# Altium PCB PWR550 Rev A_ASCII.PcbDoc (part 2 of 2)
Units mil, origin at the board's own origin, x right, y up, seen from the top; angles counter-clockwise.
Board outline 5200 x 2850 mil, 4 copper layers (Top Layer, INTERNAL 1, INTERNAL 2, Bottom Layer), stack 60.3 mil thick; 145 components, 78 nets, 363 pads, 156 vias.
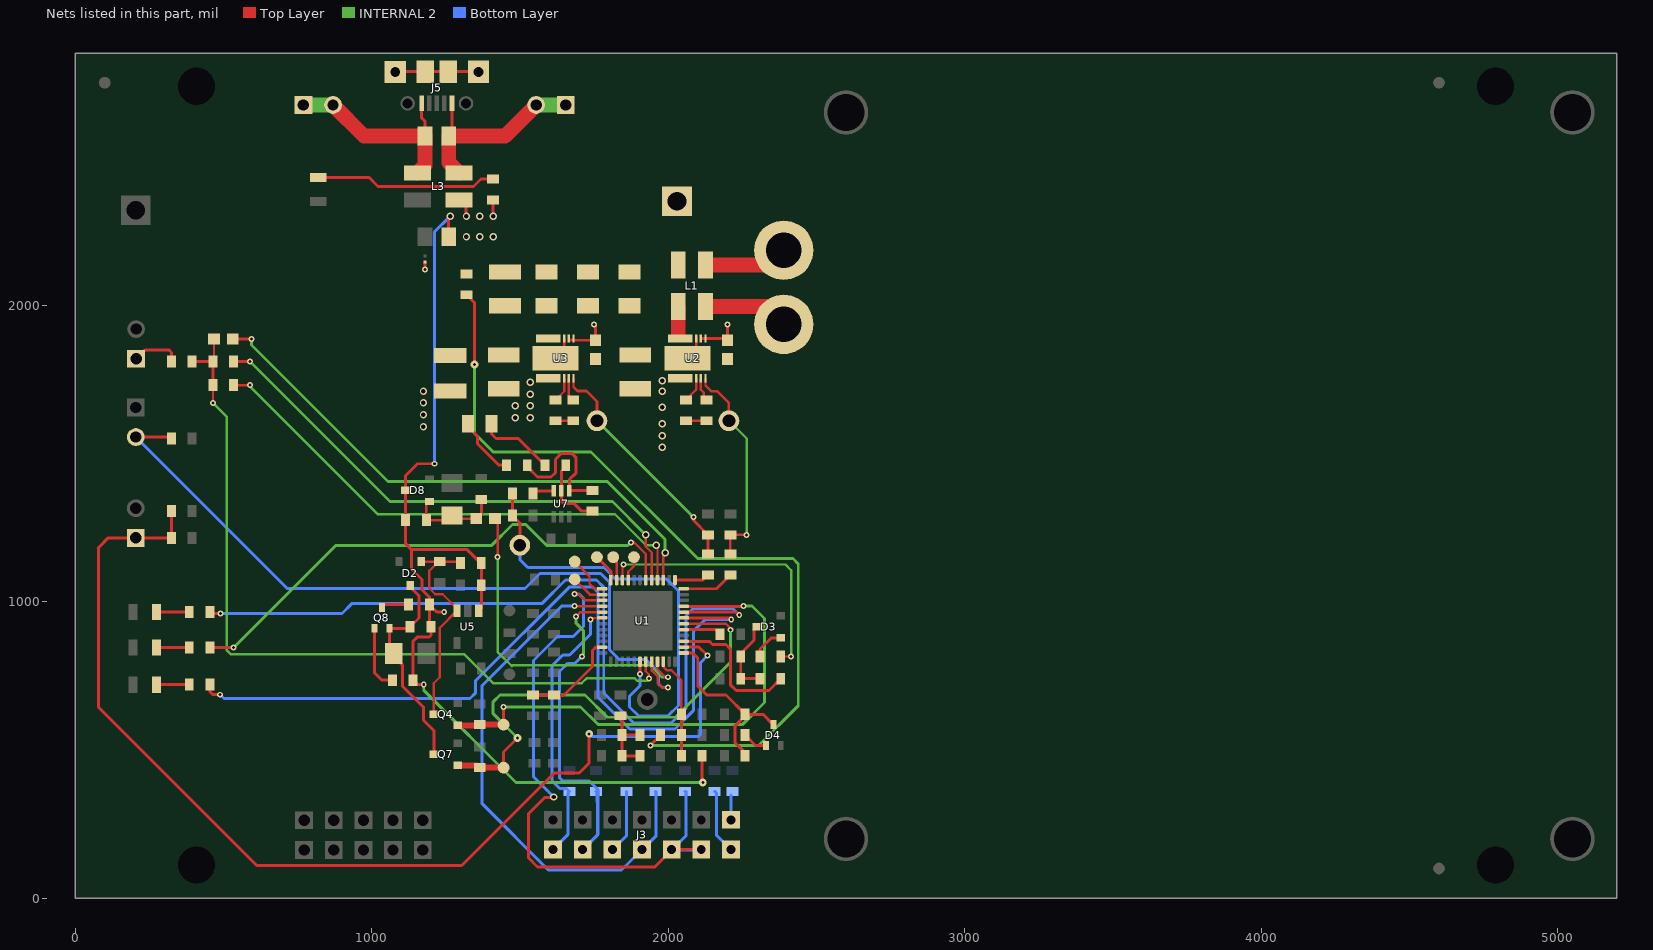
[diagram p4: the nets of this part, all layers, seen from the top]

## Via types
v1: diameter 25, hole 15, Top Layer to Bottom Layer, tented both sides, 50 vias
v2: diameter 20, hole 10, Top Layer to Bottom Layer, tented both sides, 47 vias
v3: diameter 26, hole 10, Top Layer to Bottom Layer, tented both sides, 34 vias
v4: diameter 23.62, hole 11.81, Top Layer to Bottom Layer, tented bottom, 25 vias

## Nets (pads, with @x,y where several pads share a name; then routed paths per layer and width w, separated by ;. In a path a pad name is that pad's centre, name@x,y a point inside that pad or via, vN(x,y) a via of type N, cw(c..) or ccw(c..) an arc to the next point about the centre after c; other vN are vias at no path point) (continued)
DPWM-1A: R2.1 R17.2 TP3.1 U2.8 | length 717.4
  Top Layer w8: U2.8@2126.02,1753.07 2126.02,1728.98 2145,1710 2165,1710 2205,1670 TP3.1@2205,1610 ; R2.1@2210,1160 R17.2@2210,1225 v2(2265,1225)
  INTERNAL 2 w8: TP3.1@2205,1610 2265,1550 v2(2265,1225)
DPWM-1B: R47.1 R48.2 TP2.1 U3.8 | length 798.7
  Top Layer w8: U3.8@1681.02,1753.07 1681.02,1723.98 1695,1710
  Top Layer w10: 1695,1710 1725,1710 1760,1675 TP2.1@1760,1610 ; v2(2085,1285) 2085,1275 R48.2@2135,1225 R47.1@2135,1160
  INTERNAL 2 w10: TP2.1@1760,1610 v2(2085,1285)
GND: 1A1.1 C7.1 C9.2 C13.2 C23.2 C33.2 U2.3 U2.9 U3.3 U3.9 | length 129.3
  Top Layer w8: U3.9@1649.53,1820 U3.3@1649.53,1886.93 ; U2.9@2094.53,1849.53 U2.3@2094.53,1886.93
  Top Layer w10: v2(1180,2120) 1A1.1@1180,2145
I_SENSE: C16.2 R46.1 TP19.1 U1.42 | length 1557.6
  Top Layer w10: R46.1@1475,1365 C16.2@1475,1290 1500,1265 TP19.1@1500,1190 ; v2(1905.2,756.27) U1.42@1905.2,797.6
  Bottom Layer w10: TP19.1@1500,1190 1500,1142 1527,1115 1783.5,1115 1823,1075.5 1995.37,1075.5 2035,1035.87 2035,650 2000,615 1900,615 1870,645 1870,681.06 1905.2,716.26 v2(1905.2,756.27) ; v2@1900,754.8 v2@1900.2,755
LED_A: R15.1 U1.7 | length 2850.3
  Top Layer w10: R15.1@455,720 455,696 465,686 v2(489,686) ; U1.7@2052.5,944.9 2207.1,944.9 v2(2213,939) ; v2@2209.8,939.8 v2@2209.8,940
  Bottom Layer w10: v2(489,686) 502,673 1332,673 1350,691 1350,732 1668,1050 1745,1050 1763,1032 1763,678.06 1871.06,570 2023,570 2085,632 2085,900 2120,935 cw(c2129.66,925.34) 2129.66,939 v2(2213,939)
LED_B: R16.1 U1.8 | length 2799.2
  Top Layer w10: R16.1@455,965 455,960 485,960 v2(490,960) ; U1.8@2052.5,964.6 2229.6,964.6 2239.2,955 v2(2240,955)
  Bottom Layer w10: v2(490,960) 485,960 900,960 933,993 1574,993 1654,1073 1758.25,1073 1783,1048.25 1783,692 1885,590 2010,590 2060,640 2060,952 2085,977 2218,977 v2(2240,955)
LED_C: R50.1 U1.18 | length 1779
  Top Layer w8: v2(1875,1200) 1885,1200 1924.9,1160.1 U1.18@1924.9,1072.6
  Top Layer w10: R50.1@455,845 v2(535,845)
  INTERNAL 2 w10: v2(535,845) 880,1190 1405,1190 1475,1260 1520,1260 1590,1190 1865,1190 v2(1875,1200)
NetC4_1: C4.1 R10.1 R11.2 U1.46 | length 352.2
  Top Layer w8: U1.46@1985,796.6 1985,779 1994.9,769.1 2010.9,769.1 2045,735 C4.1@2045,620
  Top Layer w10: U1.46@1984,797.6 U1.46@1985,796.6 ; R10.1@2045,480 R11.2@2045,550 C4.1@2045,620
NetC6_1: C6.1 U2.7 | length 81.2
  Top Layer w8: U2.7@2110.28,1753.07 2110.28,1715 2120,1705.28 2120,1690 C6.1@2130,1680
NetC6_2: C6.2 R3.1 | length 70
  Top Layer w10: R3.1@2060,1610 C6.2@2130,1610
NetC8_2: C8.2 C20.1 U1.35 | length 331
  Top Layer w10: C8.2@1545,685 C20.1@1615,685 1649,685 1745,781 1745,835 1756.4,846.4 U1.35@1777.5,846.4
NetC10_2: C10.2 D4.3 R8.2 U1.1 | length 627.3
  Top Layer w10: U1.1@2052.5,826.7 2083.3,826.7 2100,810 2100,715 2130,685 2195,685 C10.2@2260,620 ; R8.2@2260,480 2260,490 2225,525 2225,580 2260,615 C10.2@2260,620 ; D4.3@2355,585 2320,620 C10.2@2260,620
NetC11_1: C11.1 D3.3 R28.2 R30.1 | length 262.7
  Top Layer w10: D3.3@2299.75,915 2290,905.25 2290,870 2245,825 C11.1@2245,815 R28.2@2245,740 R30.1@2310,740
NetC12_2: C12.2 D8.1 R45.2 R51.2 R54.1 | length 317.5
  Top Layer w8: D8.1@1195.25,1337.6 1185,1327.35 R54.1@1185,1275 1255,1275 1270,1290 1280,1280 R45.2@1353.5,1280
  Top Layer w10: R45.2@1353.5,1280 1370,1296.5 R51.2@1370,1345
NetC14_2: C14.2 R5.2 R6.1 R14.1 R29.1 | length 260
  Top Layer w10: R29.1@1840,615 1845,615 R5.2@1845,550 ; R14.1@1905,480 C14.2@1845,480 R5.2@1845,550 ; R6.1@1905,550 R5.2@1845,550
NetC15_1: C15.1 R1.2 | length 60
  Top Layer w10: R1.2@1620,1610 C15.1@1680,1610
NetC15_2: C15.2 U3.7 | length 79.2
  Top Layer w8: U3.7@1665.28,1753.07 1665.28,1694.72 C15.2@1680,1680
NetC17_1: C17.1 J1.1 J1.2 J5.1 L3.1 | length 693
  Top Layer w10: C17.1@1260,2570 1271.18,2581.18 J5.1@1271.18,2681.42
  Top Layer w50: L3.1@1295,2446 1260,2481 C17.1@1260,2570 1450,2570 J1.2@1555,2675
  INTERNAL 2 w50: J1.2@1555,2675 J1.1@1655,2675
NetC17_2: C17.2 J2.1 J2.2 J5.5 L3.4 | length 703.9
  Top Layer w10: J5.5@1168.82,2681.42 1168.82,2631.18 1180,2620 C17.2@1180,2570
  Top Layer w50: J2.2@870,2675 975,2570 C17.2@1180,2570 1180,2471 L3.4@1155,2446
  INTERNAL 2 w50: J2.1@770,2675 J2.2@870,2675
NetC18_1: C18.1 R6.2 | length 2835
  Top Layer w10: C18.1@1320,2035 1347,2008 v3(1347,1800) ; v2@1940,515 R6.2@1975,550
  INTERNAL 2 w10: v3(1347,1800) 1347,1568 1410,1505 1740,1505 2100,1145 2421.21,1145 2439,1127.21 2439,649 2305,515 v2@1940,515
  other v2: 1940.8,515
NetC18_2: C18.2 C27.2 C28.2 C29.2 C30.2 L1.3 TP1.1
NetC22_2: C22.2 D2.1 Q4.3 R25.1 U5.3 | length 745.4
  Top Layer w8: D2.1@1167.65,1135 C22.2@1220,1135 ; Q4.3@1209.75,620 1209.75,724.75 1230,745 1230,911.5 U5.3@1288,969.5 1288,977 1240,1025 1215,1025 1195,1045 1195,1104 1220,1129 C22.2@1220,1135 ; R25.1@1300,1130 1295,1135 C22.2@1230,1135 C22.2@1220,1135
NetC23_1: C23.1 C33.1 R32.1 R36.1 U2.5 U3.5 | length 258.5
  Top Layer w10: R32.1@1405,1600 1405,1565 1420,1550 1495,1550 R36.1@1585,1460
  other v1: 1980,1520 1980,1560 1980,1600 1485,1620 1535,1620 1980,1655 1485,1660 1535,1660 1535,1700 1980,1710 1535,1740 1980,1745
NetC24_1: C24.1 JP1.1 R19.1 U1.2 | length 3755
  Top Layer w10: C24.1@325,1305 R19.1@325,1215 JP1.1@205,1215 112,1215 79,1182 79,644 613,110 1304,110 1616,422 1700,422 1734,456 v3(1734,554) ; U1.2@2052.5,846.4 2104.6,846.4 v2(2133,818)
  Bottom Layer w10: v3(1734,554) 1743,545 2102,545 2110,553 2110,795 v2(2133,818)
NetC27_1: C27.1 C28.1 C29.1 C30.1 U3.4
NetC31_1: C31.1 R36.2 U7.5 | length 251.6
  Top Layer w10: R36.2@1655,1460 1655,1445 1645,1445 1640.1,1440.1 U7.5@1640.1,1373.6 1640,1373.5 1640,1340 1650,1330 1683.7,1330 1708.7,1305 C31.1@1745,1305
NetC31_2: C31.2 R37.2 U7.4 | length 447
  Top Layer w10: R37.2@1525,1460 1525,1455 1560,1420 1605,1420 1620,1435 1620,1480 1640,1500 1675,1500 1690,1485 1690,1435 1667.5,1412.5 1667.5,1375 C31.2@1745,1375
NetC32_1: C32.1 D2.3 Q7.3 Q8.1 R53.1 | length 680.7
  Top Layer w10: C32.1@1060,840 Q8.1@1060,910 R53.1@1125,910 ; C32.1@1075,815 1105,785 1105,714 1175,644 1175,600 1209.75,565.25 Q7.3@1209.75,485 ; R53.1@1130,915 1160,945 1160,1020 D2.3@1130,1050
NetC34_1: C34.1 Q8.2 | length 220.4
  Top Layer w10: Q8.2@1010,910 1010,760 1035,735 C34.1@1070,735
NetD1_2: D1.2 R4.1 | length 612.8
  Top Layer w10: D1.2@820,2430 992,2430 1022,2400 1344,2400 1369,2425 R4.1@1410,2425
NetD3_1: D3.1 R33.1 | length 110.8
  Top Layer w10: R33.1@2310,815 2310,840 2347.6,877.6 D3.1@2380.25,877.6
NetD4_1: D4.1 R12.2 | length 84.5
  Top Layer w10: R12.2@2260,550 2295,515 D4.1@2330,515
NetD5_2: D5.2 R15.2 | length 110
  Top Layer w10: D5.2@275,720 R15.2@385,720
NetD7_2: D7.2 R16.2 | length 110
  Top Layer w10: D7.2@275,965 R16.2@385,965
NetD9_2: D9.2 R50.2 | length 110
  Top Layer w10: D9.2@275,845 R50.2@385,845
NetJ3_5: J3.5 R49.2 | length 216.5
  Bottom Layer w10: J3.5@1812,164 1860,210 R49.2@1860,360
NetJ3_13: J3.13 R31.2 | length 220.5
  Bottom Layer w10: R31.2@2157,360 2162.5,354.5 2162.5,212.5 J3.13@2212.5,162.5
NetJ3_14: J3.14 R21.2 | length 85
  Bottom Layer w10: J3.14@2212.5,262.5 2212.5,264 R21.2@2212.5,347.5
NetJ5_6: J5.6 J5.7 J5.8 J5.9 | length 280.5
  Top Layer w10: J5.9@1079.84,2787.32 1080.24,2787.72 1180.63,2787.72 1258.98,2787.72 J5.6@1360.16,2787.72
NetJP2_2: JP2.2 R23.2 U1.44 | length 2587.9
  Top Layer w8: U1.44@1944.6,797.6 1944.6,767.4 1965,747 1965,725 1980,710 v2(2000,710)
  Top Layer w10: JP2.2@205,1555 320,1555 R23.2@325,1550
  Bottom Layer w10: JP2.2@205,1555 715.5,1044.5 1517.5,1044.5 1568,1095 1772.5,1095 1802,1065.5 1802,838 1835,805 1925,805 1968.5,761.5 1968.5,721.5 1980,710 v2(2000,710)
NetJP3_1: JP3.1 R22.1 | length 180.1
  Top Layer w10: JP3.1@206,1819 225,1815 225,1837 237,1849 316,1849 325,1840 R22.1@325,1810
NetL1_1: L1.1 L2.2 | length 324
  Top Layer w10: L2.2@2330,1995 2390,1995 L2.2@2390,1935
  Top Layer w50: L1.1@2126,1995 L2.2@2330,1995
NetL1_2: L1.2 U2.4 | length 98.7
  Top Layer w10: U2.4@2034,1886.93 U2.4@2041.38,1886.93
  Top Layer w50: 2034,1903.72 L1.2@2034,1995
NetL1_4: L1.4 L2.1 | length 284.7
  Top Layer w50: L1.4@2126,2135 2340,2135 L2.1@2390,2185
NetQ8_3: Q8.3 R55.1 | length 105
  Top Layer w10: Q8.3@1035,980 1035,990 R55.1@1130,990
NetR1_1: R1.1 U3.6 | length 85.3
  Top Layer w8: R1.1@1620,1680 1649.53,1709.53 U3.6@1649.53,1753.07
NetR2_2: R2.2 U1.12 | length 176.8
  Top Layer w10: U1.12@2052.5,1043.4 2163.4,1043.4 R2.2@2210,1090
NetR3_2: R3.2 U2.6 | length 87.4
  Top Layer w8: R3.2@2060,1680 2094.53,1714.53 U2.6@2094.53,1753.07
NetR9_1: R9.1 U1.5 | length 135.9
  Top Layer w10: U1.5@2052.5,905.5 2159.5,905.5 R9.1@2175,890 R9.1@2175,897
NetR22_2: R22.2 R24.1 R27.1 R99.1 U1.43 | length 2679.5
  Top Layer w8: v2(465,1670) R27.1@465,1730 ; R24.1@468.5,1813.5 R99.1@468.5,1885 ; U1.43@1924.9,797.6 1924.9,765.1 1935,755 v2(1935,740)
  Top Layer w10: R22.2@395,1810 R24.1@465,1810 R27.1@465,1730
  INTERNAL 2 w8: v2(465,1670) 512,1623 512,835.47 525.47,822 1313,822 1410,725 1709,725 1726,742 1886.95,742 1895.67,733.27 1928.27,733.27 v2(1935,740)
NetR24_2: R24.2 U1.17 | length 1792.8
  Top Layer w8: v1(1925,1225) 1925,1185 1944.6,1165.4 U1.17@1944.6,1072.6
  Top Layer w10: R24.2@535,1810 v2(590,1810)
  INTERNAL 2 w10: v2(590,1810) 1062.12,1337.88 1812.12,1337.88 v1(1925,1225)
NetR27_2: R27.2 U1.16 | length 1770.8
  Top Layer w8: R27.2@535,1730 v2(590,1730) ; v1(1960,1190) 1964.3,1185.7 U1.16@1964.3,1072.6
  INTERNAL 2 w8: v2(590,1730) 590,1725 1020,1295 1820,1295 1925,1190 v1(1960,1190)
NetR46_2: R46.2 U7.6 | length 77.7
  Top Layer w10: R46.2@1545,1365 1545,1373.6 U7.6@1614.1,1373.6
NetR47_2: R47.2 U1.13 | length 118.8
  Top Layer w10: U1.13@2023.4,1072.6 2117.6,1072.6 R47.2@2135,1090
NetR99_2: R99.2 U1.15 | length 1889.7
  Top Layer w8: U1.15@1984,1072.6 1984,1159 v1(1990,1165)
  Top Layer w10: R99.2@531.5,1885 v2(595,1885)
  INTERNAL 2 w10: v2(595,1885) 595,1865 1055,1405 1795,1405 1990,1210 v1(1990,1165)
NetTP18_1: TP18.1 U1.21 | length 85.4
  Top Layer w8: U1.21@1865.8,1072.6 1865.8,1100.8 1885,1120 TP18.1@1885,1150
NetTP25_1: TP25.1 U1.26 | length 113.7
  Top Layer w8: TP25.1@1685,1075 1736.3,1023.7 U1.26@1777.5,1023.7
NetTP26_1: TP26.1 U1.25 | length 145.1
  Top Layer w8: TP26.1@1685,1135 1735,1085 1735,1060 1751.6,1043.4 U1.25@1777.5,1043.4
NetTP27_1: TP27.1 U1.24 | length 96.7
  Top Layer w10: TP27.1@1760,1150 1806.7,1103.3 U1.24@1806.7,1072.6
NetTP28_1: TP28.1 U1.23 | length 82.1
  Top Layer w8: TP28.1@1815,1150 1826.4,1138.6 U1.23@1826.4,1072.6
PWR_UP: R45.1 U1.45 | length 1135.2
  Top Layer w8: R45.1@1416.5,1280 1425,1271.5 v2(1425,1150) ; U1.45@1964.3,797.6 1964.3,771.7 1991,745 v2@1997.79,745
  INTERNAL 2 w8: v2(1425,1150) 1425,830 1472.5,782.5 ; 1472.5,785 1939.12,785 1979.12,745 v2(2000,745)
SLEEP: Q7.1 R52.2 TP20.1 U1.6 | length 1636.4
  Top Layer w8: U1.6@2052.5,925.2 2194.8,925.2 2215,905 v2(2210,905)
  Top Layer w10: TP20.1@1445,440 1445,493 v3(1492,540)
  Top Layer w20: Q7.1@1290.25,447.6 1357.4,447.6 R52.2@1365,440 TP20.1@1445,440
  INTERNAL 2 w10: v3(1492,540) 1410,622 1410,662 1433,685 1720,685 1795,610 2025,610 2210,795 v2(2210,905)
SNOOZE: Q4.1 R18.2 TP14.1 U1.9 | length 1724.8
  Top Layer w10: TP14.1@1445,585 v2(1445,645) ; U1.9@2052.5,984.3 2254.3,984.3 v2(2255,985)
  Top Layer w20: Q4.1@1290.25,582.6 1362.6,582.6 R18.2@1365,585 TP14.1@1445,585
  INTERNAL 2 w10: v2(1445,645) 1705,645 1765,585 2250,585 2325,660 2325,943 2283,985 v2(2255,985)
SNOOZE_CAP: R30.2 U1.3 | length 483.2
  Top Layer w10: U1.3@2052.5,866.1 2138.9,866.1 2150,855 2195,855 2210,840 2210,720 2230,700 2340,700 R30.2@2380,740
SNOOZE_CHG: R33.2 U1.22 | length 954.7
  Top Layer w8: U1.22@1846.1,1072.6 1846.1,1121.1 v2(1850,1125) ; R33.2@2380,815 v2(2415,815)
  INTERNAL 2 w8: v2@1850,1130 1855,1125 2395.53,1125 2415,1105.53 v2(2415,815)
TCK: J3.9 J3.11 R35.2 U1.27 | length 2230.6
  Top Layer w8: v2(1685,1025) 1700,1025 1721,1004 U1.27@1777.5,1004
  Top Layer w10: v1@1615,340 1585,340 1530,285 1530,135 1560,105 1955,105 2012.5,162.5 J3.11@2110,165 ; J3.9@2012,164 2095,165 J3.11@2110,165 ; J3.11@2112.5,162.5 J3.11@2110,165
  Bottom Layer w10: v1(1614,341) 1546,409 1546,801 1627,882 1680,882 1714,916 1714,1011 1700,1025 v2(1685,1025) ; R35.2@2057,360 2060,360 2060,210 2012.5,162.5 J3.11@2112.5,162.5
TDI: J3.3 R39.2 U1.29 | length 1290
  Top Layer w8: v2(1690,950) 1704.6,964.6 U1.29@1777.5,964.6
  INTERNAL 2 w10: v2(1690,950) 1690,927 1715,902 1715,820 v2(1710,815)
  Bottom Layer w10: v2@1710,816 1686,792 1662,792 1634,764 1634,406 1645,395 1734,395 1763,366 1763,215 1762.5,214.5 ; R39.2@1757,360 1761,360 1761,355 1760,355 1762.5,290 1762.5,214.5 ; 1762.5,214.5 1762.5,212.5 1712.5,162.5 J3.3@1712,164 1762.5,214.5
TDO: J3.7 R38.2 U1.28 | length 1796.5
  Top Layer w8: v2@1685.7,984.3 U1.28@1777.5,984.3
  Top Layer w10: v2(1685,985) v2@1685.7,984.3
  Bottom Layer w10: v2(1685,985) 1641,985 1373,717 1373,318 1596,95 1843,95 J3.7@1912,164 1912.5,162.5 1960,210 1960,360 R38.2@1957,360
TMS: J3.1 R42.2 U1.30 | length 947.5
  Top Layer w8: v2(1738,939) 1743.9,944.9 U1.30@1777.5,944.9
  Bottom Layer w10: J3.1@1612,164 1662,214 1662,355 R42.2@1667,360 1657,370 1635,370 1608,397 1608,783 1645,820 1668.26,820 1738,889.74 v2@1738,936.9 ; v2@1735.9,939 v2@1738,936.9 ; v2(1738,939) v2@1738,936.9
VIN: C2.1 C7.2 C9.1 C13.1 C26.2 C34.2 D8.3 L3.2 R4.2 R10.2 R25.2 R32.2 R37.1 R53.2 R54.2 R55.2 U2.1 U2.2 U3.1 U3.2 U5.1 | length 4146.7
  Top Layer w10: v2(1176,721) 1154,721 C34.2@1140,735 1140,866.28 1153.72,880 1194,880 1200,886 R53.2@1200,915 1195,920 R55.2@1195,990 ; v2(1212,1465) 1155,1465 1114.75,1424.75 D8.3@1114.75,1375 1115,1374.75 R54.2@1115,1275 1115,1195 1135,1175 ; v2(1245,965) 1220,965 R55.2@1195,990 ; C2.1@1260,2230 1260,2295 v1(1265,2300) ; L3.2@1295,2354 1318,2354 1318,2302 v1(1320,2300) ; R32.2@1325,1600 1325,1590 1357.5,1557.5 1357.5,1532.5 1430,1460 R37.1@1455,1460 ; U5.1@1362,969.5 1362,977.5 1370,977.5 C26.2@1370,1055 R25.2@1370,1128 ; R25.2@1370,1130 R25.2@1370,1128 ; v1(1410,2300) R4.2@1410,2355 ; 1670,1881.93 1681.02,1881.93 1686.46,1881.5 C13.1@1755,1881.5 1755,1930 v2(1750,1935) ; U2.2@2113,1886.93 U2.1@2126.02,1886.93 2194.57,1886.93 C9.1@2200,1881.5 v2(2200,1935) ; R10.2@2115,480 2115,392 v3(2117,390) ; 1135,1175 1135,1110 1170,1075 1170,1040 1195,1015 R55.2@1195,990 ; 1135,1175 1323,1175 R25.2@1370,1128
  INTERNAL 2 w10: v2(1176,721) 1176,701.37 1487.37,390 v3(2117,390)
  Bottom Layer w10: v2(1212,1465) 1212,2247 v1(1265,2300)
  other v1: 1175,1590 1175,1630 1175,1670 1175,1710 1320,2230 1365,2230 1410,2230 1365,2300
pads on no net: D2.2 D3.2 D4.2 D8.2 FID1.1 FID2.1 FID3.1 J3.6 J4.1 J4.2 J4.3 J4.4 J4.5 J4.7 J4.8 J5.2 J5.3 J5.4 J5.10 J5.11 SH-J1.0 U1.4 U1.14 U1.19 U1.41 U5.4

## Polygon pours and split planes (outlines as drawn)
NetC23_1 on Top Layer "NetC23-1-1" (solid, pour order 81): 1825,1765 2035,1765 2035,1505 1825,1505
NetC23_1 on Top Layer "NetC23-1" (solid, pour order 80): 1385,1765 1635,1765 1635,1582.19 1630.1,1570 1385,1570
VIN on Top Layer "Top-Vin-4" (solid, pour order 78): 1140,1729.37 1344.37,1729.37 1345,1730 1345,1570 1140,1570
NetC18_2 on Top Layer "NETC18-2" (solid, pour order 82): 2080,2305 2080,2085 1300,2085 1300,2155 1980,2155 1980,2305
GND on Top Layer "Top-GND-1" (solid, pour order 83): 1140,2155 2240,2155 2240,1680 1140,1680
AGND on Top Layer "Top-AGND 3" (solid, remove dead copper, pour order 84): 2600,2520 2600,1477.5 2487.5,1477.5 2487.5,1360 2600,1360 2600,335 5127.5,335 5127.5,2520
VIN on Top Layer "Top-VIN-3" (solid, pour order 77): 1250,2370 1430,2370 1430,2200 1250,2200
NetC27_1 on Top Layer "NETC27-1" (solid, pour order 79): 1925,2025 1925,1960 1635,1960 1635,1890 1560,1890 1560,1960 1395,1960 1395,2025
AGND on Top Layer "Top-No Net" (solid, pour order 85): 25,2390.78 2555,2390.78 2560,2395 2560,25 25,25
VIN on INTERNAL 2 "VIN" (solid, pour order 90): 655,2450 2220,2450 2220,1890 2225,1885 2210,1870 655,1870
AGND on INTERNAL 2 "INTERNAL 2-AGND 1" (solid, remove dead copper, pour order 91): 35,425 2535,425 2535,2430 35,2430
NetC23_1 on INTERNAL 2 "INTERNAL 2-C23_1-1" (solid, pour order 89): 1385,1765 2010,1765 2010,1500 1385,1500
VIN on INTERNAL 2 "Vin" (solid, pour order 88): 1145,1875 1145,1455 1155,1445 1300,1445 1300,1755 1300,1875
AGND on INTERNAL 1 "INTERNAL 1-AGND" (solid, remove dead copper, pour order 87): 35,20 2535,20 2535,2430 35,2430
GND on INTERNAL 1 "INTERNAL 1-GND-1" (solid, pour order 86): 1140,2155 2240,2155 2240,1680 1140,1680
AGND on Bottom Layer "Bottom-AGND 3" (solid, remove dead copper, pour order 93): 31.01,2375.25 2431.01,2375.25 2431.01,45.25 31.01,45.25
AGND on Bottom Layer "Bottom-AGND 4" (solid, remove dead copper, pour order 92): 2600,2520 2600,335 5127.5,335 5127.5,2520

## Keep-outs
Keep-Out Layer:
  the board outline again, w10
  text ".Layer_Name" at 577,-858.49 h60

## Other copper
Top Layer:
  text ".Layer_Name" at 577,-858.49 h60
INTERNAL 1:
  text ".Layer_Name" at 569,-860.49 h60
INTERNAL 2:
  text ".Layer_Name" at 578,-860 h60
Bottom Layer:
  text ".Layer_Name" at 577,-858.49 h60
Multi-Layer:
  lines w10: 6489,-374 6489,-219

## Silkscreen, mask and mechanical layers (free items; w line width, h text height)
Top Overlay:
  lines w3.94: 878.53,1169.78 880,1171.26 880,1270 1020,1270 1020,1170 ; 880,1170 1020,1170 ; 1040,1090 1060,1090 ; 1205,1160 1195,1170 1020,1170 ; 2130,655 2145,670 2400,670 2430,640 ; 2290,470 2310,450 2430,450 ; 2430,450 2430,320 2530,320 2530,450 2430,450 ; 2430,640 2430,500 2530,500 2530,640 2430,640 ; 935,1020 935,1065 935,1150 1040,1150 1040,1020 935,1020
  lines w8: 1655,1105 1660,1100
  lines w40: 2812.5,357.5 2812.5,2457.5 4912.5,2457.5 4912.5,357.5 2812.5,357.5
  text "GND" at 466,2635 h125
  text "5 VDC" at 1750,2630 h125
  text "R20" at 1100,2360 h50 r90
  text "R13" at 1380,2360 h50 r90
  text "R44" at 1980,2100 h50 r90
  text "LOSS THR" at 40,2000 h75
  text "R34" at 1980,1960 h50 r90
  text "1" at 1715,1670 h25
  text "PWM2" at 2265,1580 h50
  text "PWM1" at 1680,1490 h50
  text "LED MODE" at 40,1410 h75
  text "ISENS" at 1440,1110 h50
  text "NTC" at 150,1080 h75
  text "COM+" at 1980,660 h50
  text "STATUS" at 110,560 h75
  text "bq500212AEVM-550" at 3011,153 h200
  text "PWR550A" at 3753,53 h90
  text "1" at 1387.5,30 h25
  text "1" at 540,27.5 h25
  text ".Layer_Name" at 577,-858.49 h60
Bottom Overlay:
  text ".Layer_Name" at 577,-858.49 h60
Top Paste:
  text ".Layer_Name" at 577,-858.49 h60
Bottom Paste:
  text ".Layer_Name" at 577,-858.49 h60
Top Solder:
  text ".Layer_Name" at 577,-858.49 h60
  text ".Layer_Name" at 577,-858.49 h60
Bottom Solder:
  text ".Layer_Name" at 577,-858.49 h60
Drill Guide:
  text ".Layer_Name" at 577,-858.49 h60
M1 Board Outline:
  text ".Layer_Name" at 577,-858.49 h60
M2 Board Dimensions:
  rectangle: 124.5,-410.5 499.5,-285.5
  rectangle: -0.5,-285.5 124.5,-160.5
  lines w7: -0.5,-285.5 999.5,-285.5 ; 124.5,-410.5 124.5,-160.5 ; 249.5,-410.5 249.5,-160.5 ; 499.5,-410.5 499.5,-160.5 ; 749.5,-410.5 749.5,-160.5 ; -0.5,-410.5 -0.5,-160.5 999.5,-160.5 999.5,-410.5 -0.5,-410.5
  text ".Layer_Name" at 577,-858.49 h60
M3 3D STEP Top:
  text ".Layer_Name" at 577,-858.49 h60
M4 3D STEP Bottom:
  text ".Layer_Name" at 577,-858.49 h60
M5 Assembly Top:
  lines w7: 6428,-263.5 7553,-263.5 ; 6428,-141 7550.5,-141 ; 6743,-383.5 6743,-21 ; 7128,-383.5 6428,-383.5 ; 7128,-21 6428,-21 ; 6428,-383.5 7553,-383.5 7553,-21 6428,-21 ; 6428,-383.5 6428,-21
  lines w10: -292,-930.17 6308,-930.17 ; -292,-726.83 6310,-726.83 ; -292,-523.5 -292,-1133.5 3713,-1133.5 6310,-1133.5 6310,-523.5 -291.5,-523.5 -291.5,-1133.5 1284,-1133.5 ; 2173,-1133.5 2173,-523.5 ; 3440,-726.83 3440,-523.5 ; 4280,-726.83 4280,-523.5 ; 4902,-1140 4902,-937.17
  text "TABLE 1" at 6815.5,14 h40
  text "Variant" at 6453,-96 h40
  text "Label text" at 6888,-96 h40
  text "001" at 6520.5,-216 h40
  text "ChangeMe!" at 6798,-218.5 h40
  text "COMPONENTS MARKED 'DNP' SHOULD NOT BE POPULATED, AND MAY NOT BE IN BILL OF MATERIALS" at 1153.5,-318.5 h60
  text "002" at 6520.5,-341 h40
  text "ChangeMe!" at 6793,-343.5 h40
  text "ASSEMBLY VARIANT:" at 1153,-434 h60
  text ".VariantName" at 2189,-434 h60
  text "PCB VIEWED FROM TOP SIDE" at -228.5,-655.67 h60
  text "BOARD #:" at 2248,-655.67 h60
  text ".PRJ_Number" at 2793.5,-655.67 h60
  text "REV:" at 3638,-655.67 h60
  text ".PCB_Rev" at 3929.5,-655.67 h60
  text "SVN REV:" at 4476,-655.67 h60
  text ".VersionControl_RevNumber" at 4982,-655.67 h60
  text "IGNORE ->" at -228.5,-858.49 h60
  text "PLOT NAME =" at -228.5,-1064.34 h60
  text ".plot_File_Name" at 577,-1064.34 h60
  text "GENERATED    :" at 2250,-1064.34 h60
  text ".Print_Date" at 3119.5,-1064.34 h60
  text ".Print_Time" at 3848.5,-1064.34 h60
  text "TEXAS INSTRUMENTS" at 5113,-1064.34 h60
M6 Assembly Bottom:
  lines w10: -292.5,-727.33 6309.5,-727.33 ; -290.5,-930.67 6309.5,-930.67 ; 1115.5,-1140.5 1115.5,-937.67 ; 1737.5,-727.33 1737.5,-524 ; 2577.5,-727.33 2577.5,-524 ; 3844.5,-1134 3844.5,-524 ; 4733.5,-1134 6309,-1134 6309,-524 -292.5,-524 -292.5,-1134 2304.5,-1134 6309.5,-1134 6309.5,-524
  text "COMPONENTS MARKED 'DNP' SHOULD NOT BE POPULATED, AND MAY NOT BE IN BILL OF MATERIALS" at 6102,-318 h60
  text ".VariantName" at 5058,-434 h60
  text "ASSEMBLY VARIANT:" at 6097,-434 h60
  text ".VersionControl_RevNumber" at 1035.5,-656.17 h60
  text "SVN REV:" at 1541.5,-656.17 h60
  text ".PCB_Rev" at 2088,-656.17 h60
  text "REV:" at 2379.5,-656.17 h60
  text ".PRJ_Number" at 3224,-656.17 h60
  text "BOARD #:" at 3769.5,-656.17 h60
  text "PCB VIEWED FROM BOTTOM SIDE" at 6246,-656.17 h60
  text "IGNORE ->" at 2547.85,-858.49 h60
  text "TEXAS INSTRUMENTS" at 904.5,-1064.84 h60
  text ".Print_Time" at 2169,-1064.84 h60
  text ".Print_Date" at 2898,-1064.84 h60
  text "GENERATED    :" at 3767.5,-1064.84 h60
  text ".plot_File_Name" at 5440.5,-1064.84 h60
  text "PLOT NAME =" at 6246,-1064.84 h60
M9 Title Sheet:
  lines w10: -491.5,1041.5 -291.5,1041.5 ; -491.5,3416.5 -291.5,3416.5 ; -491.5,5791.5 -291.5,5791.5 ; 2008.5,-1333.5 2008.5,-1133.5 ; 2008.5,7966.5 2008.5,8166.5 ; 4508.5,-1333.5 4508.5,-1133.5 ; 4508.5,7966.5 4508.5,8166.5 ; 6321,-1133.5 6321,-523.5 11303.5,-523.5 ; 7008.5,-1333.5 7008.5,-1133.5 ; 7008.5,7966.5 7008.5,8166.5 ; 9508.5,-1333.5 9508.5,-1133.5 ; 9508.5,7966.5 9508.5,8166.5 ; 11303.5,-1133.5 11303.5,-523.5 ; 11303.5,-823.5 14303.5,-823.5 ; 11303.5,-223.5 14303.5,-223.5 ; 11304.5,370.5 14304.5,370.5 ; 12008.5,-1333.5 12008.5,-1133.5 ; 12008.5,7966.5 12008.5,8166.5 ; 12808.5,-1123.5 12808.5,-523.5 ; 14303.5,-523.5 11303.5,-523.5 ; 14303.5,76.5 11303.5,76.5 ; 14308.5,66.5 14308.5,-1133.5 ; 14308.5,871 11304.5,871 11303.5,871 11303.5,370.5 11303.5,76.5 ; 14308.5,1041.5 14508.5,1041.5 ; 14308.5,3416.5 14508.5,3416.5 ; 14308.5,5791.5 14508.5,5791.5 ; 11303.5,-523.5 11303.5,76.5 ; 14308.5,-1133.5 -291.5,-1133.5 -291.5,7966.5 14308.5,7966.5 14308.5,-1133.5 ; -491.5,-1333.5 14508.5,-1333.5 14508.5,8166.5 -491.5,8166.5 -491.5,-1333.5
  text "1" at 739.84,8036.5 h70
  text "2" at 3235.5,8036.5 h70
  text "3" at 5724.84,8036.5 h70
  text "4" at 8231.51,8036.5 h70
  text "5" at 10730.5,8036.5 h70
  text "6" at 13235.5,8036.5 h70
  text "A" at -416.5,6893.5 h70
  text "A" at 14383.5,6893.5 h70
  text "B" at -416.5,4513.5 h70
  text "B" at 14383.5,4513.5 h70
  text "C" at -416.5,2138.5 h70
  text "C" at 14383.5,2138.5 h70
  text "PROJECT TITLE:" at 11343.5,277.5 h45
  text ".PRJ_Title" at 11393.5,144.17 h70
  text "DESIGNED FOR:" at 11343.5,-23.5 h45
  text ".PRJ_Customer" at 11393.5,-163.5 h70
  text "D" at -416.5,-231.5 h70
  text "D" at 14383.5,-231.5 h70
  text "FILE NAME:" at 11343.5,-323.5 h45
  text ".PCB_File_Name_No_Path" at 11393.5,-443.5 h70
  text "Texas Instruments (TI) and/or its licensors do not warrant the accuracy or completeness of this specification" at 6374,-605.34 h45
  text "ENGINEER:" at 11343.5,-613.5 h45
  text "LAYOUT BY:" at 12848.5,-613.5 h45
  text "or any information contained therein. TI and/or its licensors do not warrant that this design will meet" at 6329.01,-718 h45
  text ".PRJ_Engineer" at 11393.5,-768.49 h70
  text ".PCB_Layout" at 12899,-768.49 h70
  text "the specifications, will be suitable for your application or fit for any particular purpose, or will operate in" at 6329.01,-830.67 h45
  text ".Layer_Name" at 577,-858.49 h60
  text "ALTIUM DESIGNER VERSION:" at 12848.5,-923.5 h45
  text "an implementation. TI and/or its licensors do not warrant that the design is production worthy. You should" at 6329.01,-943.33 h45
  text "completely validate and test your design implementation to confirm the system functionality for your application." at 6374,-1056 h45
  text ".print_Scale" at 11393.5,-1056.83 h70
  text ".Application_BuildNumber" at 12899,-1056.83 h70
  text "1" at 739.84,-1263.5 h70
  text "2" at 3235.5,-1263.5 h70
  text "3" at 5724.84,-1263.5 h70
  text "4" at 8231.51,-1263.5 h70
  text "5" at 10730.5,-1263.5 h70
  text "6" at 13235.5,-1263.5 h70
M10 Fab Notes:
  drawing of 203 lines, arcs and shapes, not listed
  text "DESIGN INFORMATION" at 12381.02,6810 h60
  text "(REFER ALSO ARRAY/PANEL PROFILING INFORMATION)" at 12019.46,6648.29 h60
  text "BOARD SIZE" at 11333.46,6644 h60
  text "5200MIL" at 11795.78,6516.18 h60
  text "X" at 12301.46,6516.18 h60
  text "2850MIL" at 12532.78,6516.18 h60
  text "Number of Layers :" at 11736.46,6319 h60
  text "4" at 12831.27,6309 h60
  text "MIN. TRACK WIDTH:" at 11736.46,6180 h60
  text "8" at 12832.7,6180 h60
  text "MIL" at 12987.46,6180 h60
  text "MIN. CLEARANCE:" at 11736.46,6048 h60
  text "7" at 12832.7,6048 h60
  text "MIL" at 12987.46,6048 h60
  text "MIN. VIA PAD SIZE:" at 11736.46,5916 h60
  text "20" at 12802.71,5916 h60
  text "MIL" at 12987.46,5916 h60
  text "0.127mm (5MIL)" at 12431.46,5774.29 h60
  text "MINIMUM ANNULAR RING" at 11407.23,5770 h60
  text "EXTERNAL" at 13139.46,5770 h60
  text "PER" at 11607.23,5652 h60
  text "IPC-D-275 CLASS 2 LEVEL C" at 11827.23,5652 h60
  text "MIL, HOLES" at 13315.46,5539.71 h60
  text "+/-" at 12923,5539 h60
  text "+/-" at 13777,5539 h60
  text "REGISTRATION TOLERANCES:" at 11407.23,5534 h60
  text "METAL" at 12607,5534 h60
  text "5" at 13183.2,5534 h60
  text "3" at 14016.2,5534 h60
  text "MIL" at 14132.46,5534 h60
  text "MATERIAL:" at 11332.46,5324.54 h60
  text "FR-4 High Tg" at 12318.9,5184.21 h60
  text "FR-4" at 11793.46,5175.64 h60
  text "X" at 12165.46,5175.64 h60
  text "OTHER" at 13241.46,5175.64 h60
  text "62 MIL (1.6mm) +/-10%" at 12073.56,5012.92 h60
  text "THICKNESS:" at 11407.23,5008.64 h60
  text "X" at 11945.4,5008.64 h60
  text "OTHER" at 13358.46,5008.64 h60
  text "TOLERANCE:" at 11407.23,4850.64 h60
  text "X" at 12246.53,4850.64 h60
  text "ANSI IPC-6012 TYPE 3 CLASS 2" at 12433.48,4850.64 h60
  text "OTHER +/-" at 12433.46,4694.64 h60
  text "BOW & TWIST:" at 11407.23,4537.64 h60
  text "X" at 12246.53,4537.64 h60
  text "ANSI IPC-6012 TYPE 3 CLASS 2" at 12433.48,4537.64 h60
  text "OTHER +/-" at 12433.46,4379.13 h60
  text "COPPER THICKNESS (FINISHED):" at 11332.46,4243.64 h60
  text "1.4MIL (1oz)" at 12212.46,4090.92 h60
  text "2MIL (1.4oz)" at 12979.46,4090.92 h60
  text "2.8MIL (2oz)" at 13706.46,4090.92 h60
  text "OUTER:" at 11689.46,4086.64 h60
  text "X" at 13580,4084 h60
  text "1.4MIL (1oz)" at 12562.46,3933.92 h60
  text "2.8MIL (2oz)" at 13406.46,3933.92 h60
  text "INNER SIGNAL:" at 11689.46,3929.64 h60
  text "X" at 13283,3920 h60
  text "DRILLING:" at 11332.46,3790.64 h60
  text "REFERENCE:" at 11407.23,3673.64 h60
  text "X" at 12055.46,3673.64 h60
  text "AS SHOWN" at 12242.46,3673.64 h60
  text "X" at 12956.46,3673.64 h60
  text "NC_DRILL FILES" at 13093.46,3673.64 h60
  text "PTH MIN COPPER THICKNESS:" at 11407.23,3515.64 h60
  text "X" at 12757.46,3515.64 h60
  text "1MIL" at 12894.46,3515.64 h60
  text "OTHER" at 13391.46,3515.64 h60
  text "BOARD FINISH:" at 11332.46,3356.64 h60
  text "SILKSCREEN:" at 11487.68,3238.64 h60
  text "X" at 12436.46,3238.64 h60
  text "TOP" at 12562.46,3238.64 h60
  text "BOTTOM" at 13073.46,3238.64 h60
  text "SILKSCREEN COLOR:" at 11487.68,3071.64 h60
  text "X" at 12435.42,3071.64 h60
  text "WHITE" at 12562.46,3071.64 h60
  text "OTHER" at 13073.46,3071.64 h60
  text "SOLDER RESIST COLOR:" at 11487.68,2901.64 h60
  text "X" at 12055.42,2742.44 h60
  text "GREEN" at 12182.46,2742.44 h60
  text "BLUE" at 12773.46,2742.44 h60
  text "OTHER" at 13311.46,2742.44 h60
  text "IMMERSION GOLD (ENIG)" at 12393.46,2553.92 h60
  text "SURFACE FINISH:" at 11332.46,2549.64 h60
  text "X" at 12206.51,2549.64 h60
  text "Pb-FREE HASL" at 13625.75,2549.64 h60
  text "OTHER" at 12393.46,2392.64 h60
  text "ARRAY/PANEL:" at 11332.46,2213.64 h60
  text "CUT AND TRIM PER MECH LAYER 1" at 12393.46,2209.35 h60
  text "N.C. ROUTE" at 12393.46,2057.64 h60
  text "X" at 13072.46,2057.64 h60
  text "V. SCORE" at 13259.46,2057.64 h60
  text "CERTIFICATION:" at 11332.46,1920.64 h60
  text "MATERIALS AND WORKMANSHIP FOR ALL PCBS" at 12057.46,1920.64 h60
  text "TO MEET OR EXCEED THE REQUIREMENTS OF:" at 12057.46,1822.64 h60
  text "X" at 11683.96,1686.13 h60
  text "ANSI IPC-A-600F CLASS ->" at 11822.96,1686.13 h60
  text "X" at 13462.02,1686.13 h60
  text "2" at 13580.96,1686.14 h60
  text "1" at 13265.96,1684.64 h60
  text "3" at 13934.96,1684.64 h60
  text "X" at 11686.02,1526.64 h60
  text "UL 94V-0" at 11822.96,1526.64 h60
  text "X" at 12498.02,1526.64 h60
  text "RoHS" at 12634.96,1526.64 h60
  text "OTHER" at 13279.36,1526.64 h60
  text "PER ORDER" at 13676.42,1526.64 h60
  text "ADDITIONAL REQUIREMENTS:" at 11332.46,1385.64 h60
  text "MICROSECTION:" at 11407.23,1270.64 h60
  text "YES" at 12312.96,1270.64 h60
  text "REQUIRED" at 13174.46,1114.49 h60
  text "BARE BOARD ELEC. TEST:" at 11407.23,1111.64 h60
  text "NONE" at 12712.96,1111.64 h60
  text "X" at 13047.46,1111.64 h60
  text "PER ORDER" at 13766.46,1111.64 h60
  text "MANUFACTURER'S ID/LOGO:" at 11407.23,954.64 h60
  text "RAIL" at 12872.96,950.35 h60
  text "METAL" at 13364.77,950.35 h60
  text "SILK" at 13876.46,950.35 h60
  text "X" at 13741,946 h60
  text ".Layer_Name" at 577,-858.49 h60
M11 Gerber Information:
  lines w10: -292,-930.17 6308,-930.17 ; -292,-726.83 6310,-726.83 ; -292,-523.5 -292,-1133.5 3713,-1133.5 6310,-1133.5 6310,-523.5 -291.5,-523.5 -291.5,-1133.5 1284,-1133.5 ; 2173,-1133.5 2173,-523.5 ; 3440,-726.83 3440,-523.5 ; 4280,-726.83 4280,-523.5 ; 4902,-1140 4902,-937.17
  text "ALL ARTWORK VIEWED FROM TOP SIDE" at -228.5,-655.67 h60
  text "BOARD #:" at 2248,-655.67 h60
  text ".PRJ_Number" at 2793.5,-655.67 h60
  text "REV:" at 3638,-655.67 h60
  text ".PCB_Rev" at 3929.5,-655.67 h60
  text "SVN REV:" at 4476,-655.67 h60
  text ".VersionControl_RevNumber" at 4982,-655.67 h60
  text "LAYER NAME =" at -228.5,-858.49 h60
  text "PLOT NAME =" at -228.5,-1064.34 h60
  text ".plot_File_Name" at 577,-1064.34 h60
  text "GENERATED    :" at 2250,-1064.34 h60
  text ".Print_Date" at 3119.5,-1064.34 h60
  text ".Print_Time" at 3848.5,-1064.34 h60
  text "TEXAS INSTRUMENTS" at 5113,-1064.34 h60
M12 Stackup:
  lines w6: 9565,7698.25 14239,7698.25 ; 9565,7814.95 14239,7814.95 ; 9505,6963 ccw(c9543,6963) 9543,6925 14261,6925 ccw(c14261,6963) 14299,6963 14299,7914 ccw(c14261,7914) 14261,7952 9543,7952 ccw(c9543,7914) 9505,7914 9505,6963
  text "Layer Stack Up Detail for: PWR550 Rev A.PcbDoc" at 9565,7844.88 h52
  text "Layer" at 9565,7771.45 h27
  text "Gerber" at 10507.79,7771.45 h27
  text "Copper" at 11083.9,7771.45 h27
  text "Dielectric" at 11704.1,7771.45 h27
  text "Dielectric" at 12343.19,7771.45 h27
  text "Dielectric" at 13096.04,7771.45 h27
  text "Dielectric" at 13735.13,7771.45 h27
  text "Name" at 9565,7717.45 h27
  text "Document" at 10507.79,7717.45 h27
  text "Thickness" at 11083.9,7717.45 h27
  text "Height" at 11704.1,7717.45 h27
  text "Material" at 12343.19,7717.45 h27
  text "Constant" at 13096.04,7717.45 h27
  text "Type" at 13735.13,7717.45 h27
  text "Top Solder Mask" at 9565,7641.76 h38
  text "(.GTS)" at 10507.79,7641.76 h38
  text "0.4mil" at 11704.1,7641.76 h38
  text "Solder Resist" at 12343.19,7641.76 h38
  text "3.50" at 13096.04,7641.76 h38
  text "Top Layer" at 9565,7534.78 h38
  text "(.GTL)" at 10507.79,7534.78 h38
  text "2.8mil" at 11083.9,7534.78 h38
  text "18.3mil" at 11704.1,7481.29 h38
  text "370HR" at 12343.19,7481.29 h38
  text "4.80" at 13096.04,7481.29 h38
  text "Core" at 13735.13,7481.29 h38
  text "INTERNAL 1" at 9565,7427.8 h38
  text "(.G1)" at 10507.79,7427.8 h38
  text "2.8mil" at 11083.9,7427.8 h38
  text "12.5mil" at 11704.1,7374.31 h38
  text "370HR" at 12343.19,7374.31 h38
  text "4.80" at 13096.04,7374.31 h38
  text "PrePreg" at 13735.13,7374.31 h38
  text "INTERNAL 2" at 9565,7320.82 h38
  text "(.G2)" at 10507.79,7320.82 h38
  text "2.8mil" at 11083.9,7320.82 h38
  text "18.3mil" at 11704.1,7267.33 h38
  text "370HR" at 12343.19,7267.33 h38
  text "4.80" at 13096.04,7267.33 h38
  text "Core" at 13735.13,7267.33 h38
  text "Bottom Layer" at 9565,7213.84 h38
  text "(.GBL)" at 10507.79,7213.84 h38
  text "2.8mil" at 11083.9,7213.84 h38
  text "Bottom Solder Mask" at 9565,7106.87 h38
  text "(.GBS)" at 10507.79,7106.87 h38
  text "0.4mil" at 11704.1,7106.87 h38
  text "Solder Resist" at 12343.19,7106.87 h38
  text "3.50" at 13096.04,7106.87 h38
  text ".Layer_Name" at 577,-858.49 h60
M13 Component Bodies Top:
  text ".Layer_Name" at 577,-858.49 h60
M14 Component Bodies Bottom:
  text ".Layer_Name" at 577,-858.49 h60
M15 Courtyards Top:
  text ".Layer_Name" at 577,-858.49 h60
M16 Courtyards Bottom:
  text ".Layer_Name" at 577,-858.49 h60
Drill Drawing:
  lines w1: 0,0 0.03,0 ; 5200,2850 5200.03,2850 ; 0,2850 0.03,2850 0,2850
  lines w10: -375,0 -50,0 ; -375,2850 -50,2850 ; -325,1357.5 -325,0 ; -325,1492.5 -325,2850 ; -325,0 -300,100 -350,100 -325,0 ; -325,2850 -350,2750 -300,2750 -325,2850
  text ".legend" at 1008,4382 h60
  text ".Layer_Name" at 577,-858.49 h60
